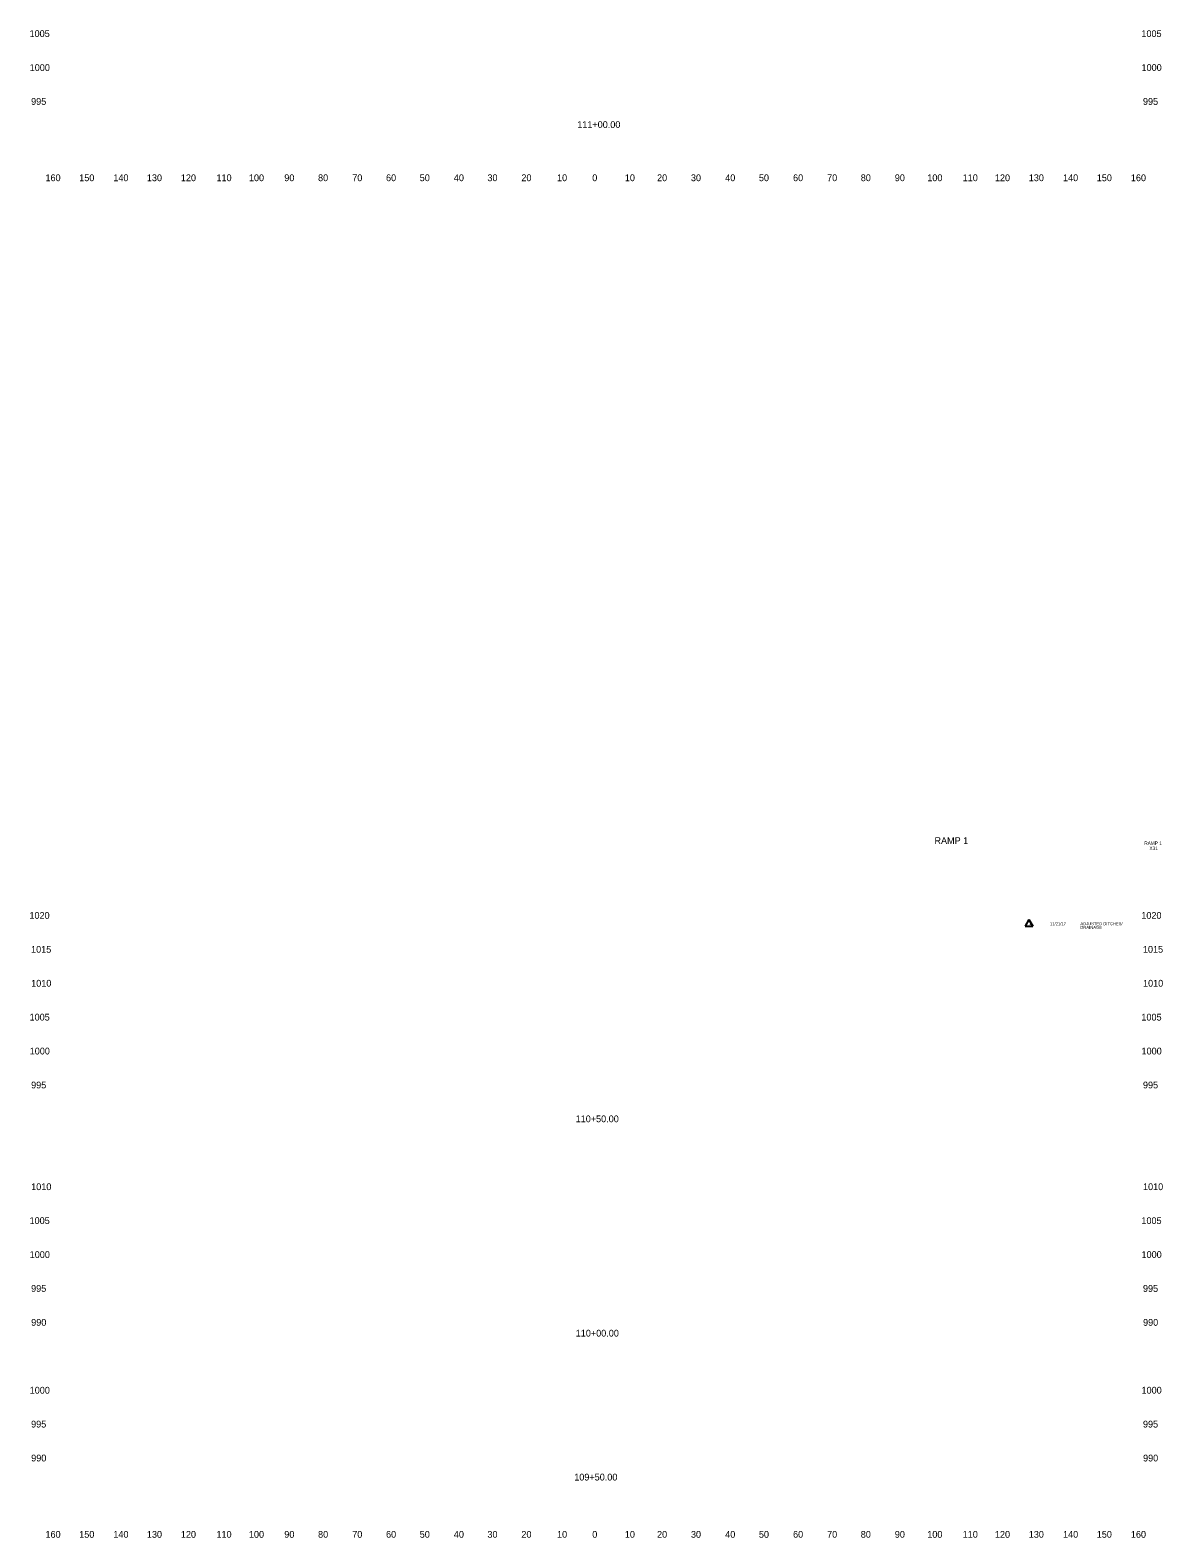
# Model space of a CAD drawing. Extents: x 4994 to 7869, y 4997 to 8804.
# Drawn here: x 6538.6 to 6872.5, y 4997.5 to 5442 of the extents above; entities that cross this region are included whole.
import ezdxf

# ---------------------------------------------------------------- set-up
doc = ezdxf.new("R2010")
doc.units = 0
for name, color, linetype in [('RD_SHT_ID', 7, 'Continuous'), ('RD_SHT_TX', 7, 'Continuous'), ('RD_XS_TX_Offset', 7, 'Continuous'), ('RD_XS_TX_Station', 7, 'Continuous')]:
    doc.layers.add(name, color=color, linetype=linetype)

msp = doc.modelspace()

# ---------------------------------------------------------------- linework, layer by layer
at = {"layer": 'RD_SHT_TX'}
for p, q in [((6833.05, 5179.83), (6831.91, 5177.8)), ((6833.05, 5179.83), (6834.19, 5177.8)), ((6831.91, 5177.8), (6834.19, 5177.8))]:
    msp.add_line(p, q, dxfattribs=at)

# ---------------------------------------------------------------- texts
at = {"layer": 'RD_SHT_ID'}
for s, height, p in [('RAMP 1', 2, (6805.19, 5202.06)), ('RAMP 1', 1, (6867.06, 5201.8)), ('X31', 1, (6868.57, 5200.3))]:
    msp.add_text(s, height=height, dxfattribs=at).set_placement(p)
at = {"layer": 'RD_SHT_TX'}
for s, p in [('1', (6833.05, 5178.13)), ('11/21/17', (6839.24, 5178.09)), ('ADJUSTED DITCHES/', (6848.22, 5178.12)), ('DRAINAGE', (6848.22, 5177.02))]:
    msp.add_text(s, height=0.88, dxfattribs=at).set_placement(p)
at = {"layer": 'RD_XS_TX_Offset'}
for s, p in [('1005', (6538.4, 5440)), ('1005', (6866.2, 5440)), ('1000', (6538.44, 5430)), ('1000', (6866.24, 5430)), ('995', (6538.86, 5420)), ('995', (6866.66, 5420)), ('160', (6543.1, 5397.5)), ('150', (6553.04, 5397.5)), ('140', (6563.1, 5397.5)), ('130', (6572.99, 5397.5)), ('120', (6583.01, 5397.5)), ('110', (6593.51, 5397.5)), ('100', (6603.07, 5397.5)), ('90', (6613.5, 5397.5)), ('80', (6623.46, 5397.5)), ('70', (6633.54, 5397.5)), ('60', (6643.5, 5397.5)), ('50', (6653.43, 5397.5)), ('40', (6663.5, 5397.5)), ('30', (6673.39, 5397.5)), ('20', (6683.4, 5397.5)), ('10', (6693.91, 5397.5)), ('0', (6704.3, 5397.5)), ('0', (6704.3, 5397.5)), ('10', (6713.91, 5397.5)), ('20', (6723.4, 5397.5)), ('30', (6733.39, 5397.5)), ('40', (6743.5, 5397.5)), ('50', (6753.43, 5397.5)), ('60', (6763.5, 5397.5)), ('70', (6773.54, 5397.5)), ('80', (6783.46, 5397.5)), ('90', (6793.5, 5397.5)), ('100', (6803.07, 5397.5)), ('110', (6813.51, 5397.5)), ('120', (6823.01, 5397.5)), ('130', (6832.99, 5397.5)), ('140', (6843.1, 5397.5)), ('150', (6853.04, 5397.5)), ('160', (6863.1, 5397.5)), ('1020', (6538.37, 5180)), ('1020', (6866.17, 5180)), ('1015', (6538.85, 5170)), ('1015', (6866.65, 5170)), ('1010', (6538.88, 5160)), ('1010', (6866.68, 5160)), ('1005', (6538.4, 5150)), ('1005', (6866.2, 5150)), ('1000', (6538.44, 5140)), ('1000', (6866.24, 5140)), ('995', (6538.86, 5130)), ('995', (6866.66, 5130)), ('1010', (6538.88, 5100)), ('1010', (6866.68, 5100)), ('1005', (6538.4, 5090)), ('1005', (6866.2, 5090)), ('1000', (6538.44, 5080)), ('1000', (6866.24, 5080)), ('995', (6538.86, 5070)), ('995', (6866.66, 5070)), ('990', (6538.89, 5060)), ('990', (6866.69, 5060)), ('1000', (6538.44, 5040)), ('1000', (6866.24, 5040)), ('995', (6538.86, 5030)), ('995', (6866.66, 5030)), ('990', (6538.89, 5020)), ('990', (6866.69, 5020)), ('160', (6543.1, 4997.5)), ('150', (6553.04, 4997.5)), ('140', (6563.1, 4997.5)), ('130', (6572.99, 4997.5)), ('120', (6583.01, 4997.5)), ('110', (6593.51, 4997.5)), ('100', (6603.07, 4997.5)), ('90', (6613.5, 4997.5)), ('80', (6623.46, 4997.5)), ('70', (6633.54, 4997.5)), ('60', (6643.5, 4997.5)), ('50', (6653.43, 4997.5)), ('40', (6663.5, 4997.5)), ('30', (6673.39, 4997.5)), ('20', (6683.4, 4997.5)), ('10', (6693.91, 4997.5)), ('0', (6704.3, 4997.5)), ('0', (6704.3, 4997.5)), ('10', (6713.91, 4997.5)), ('20', (6723.4, 4997.5)), ('30', (6733.39, 4997.5)), ('40', (6743.5, 4997.5)), ('50', (6753.43, 4997.5)), ('60', (6763.5, 4997.5)), ('70', (6773.54, 4997.5)), ('80', (6783.46, 4997.5)), ('90', (6793.5, 4997.5)), ('100', (6803.07, 4997.5)), ('110', (6813.51, 4997.5)), ('120', (6823.01, 4997.5)), ('130', (6832.99, 4997.5)), ('140', (6843.1, 4997.5)), ('150', (6853.04, 4997.5)), ('160', (6863.1, 4997.5))]:
    msp.add_text(s, height=2, dxfattribs=at).set_placement(p)
at = {"layer": 'RD_XS_TX_Station'}
for s, p in [('111+00.00', (6699.87, 5413.18)), ('110+50.00', (6699.4, 5120.02)), ('110+00.00', (6699.43, 5056.82)), ('109+50.00', (6698.99, 5014.38))]:
    msp.add_text(s, height=2, dxfattribs=at).set_placement(p)

doc.saveas('drawing.dxf')
